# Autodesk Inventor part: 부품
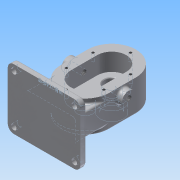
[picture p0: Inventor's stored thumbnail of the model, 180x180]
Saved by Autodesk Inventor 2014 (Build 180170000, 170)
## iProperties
Created: 2020-09
Part Number: 부품
Material: 알루미늄 6061
Document SubType Name: Modeling
Designer: net
Density: 2.71 g/cm^3
Appearance: 알루미늄 - 평지
Mass: 1445.06 g
Surface Area: 785.878 cm^2
Volume: 533.233 cm^3
Author: net
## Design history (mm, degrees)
sketch "스케치1"
  geometry: L1 (0, 0)-(0, 44); L2 (40, 0)-(40, 44); L3 (-40, 44)-(-40, 0); A1 r 40 centre (0, 0) between (-40, 0) and (40, 0); A2 r 40 centre (0, 44) between (40, 44) and (-40, 44); 1 further point
  constraints: 8 end point, 4 point on circle, 4 tangent, 2 centre point, 1 midpoint, 1 parallel, 1 vertical
  dimensions: "d0" = 44 distance of L1.start L1.end; "d1" = 80 diameter of A2
extrude "돌출1" new body sketch "스케치1" distance "d2" = 53; taper "d3" = 0 deg
sketch "스케치2"
  geometry: L1 (40, 0)-(40, 44) reference; L2 (0, 0)-(0, 44); L3 (24, 0)-(24, 44); L4 (-24, 44)-(-24, 0); A1 r 40 centre (0, 44) between (40, 44) and (-40, 44) reference; A2 r 40 centre (0, 0) between (-40, 0) and (40, 0) reference; A3 r 24 centre (0, 0) between (-24, 0) and (24, 0); A4 r 24 centre (0, 44) between (24, 44) and (-24, 44); 1 further point
  constraints: 8 end point, 4 point on circle, 4 tangent, 2 centre point, 2 parallel, 1 midpoint
  dimensions: "d4" = 48 diameter of A4
extrude "돌출2" cut sketch "스케치2" distance "d5" = 29; taper "d6" = 0 deg
sketch "스케치3"
  geometry: C1 r 19 at (0, 44); A1 r 40 centre (0, 44) between (40, 44) and (-40, 44) reference
  constraints: 1 centre point, 1 coincident
  dimensions: "d7" = 38 diameter of C1
extrude "돌출3" join sketch "스케치3" distance "d8" = 17; taper "d9" = 0 deg
sketch "스케치4"
  geometry: C1 r 8.5 at (0, 44); C2 r 12.5 at (0, 44); A1 r 24 centre (0, 44) between (24, 44) and (-24, 44) reference
  constraints: 2 centre point, 2 coincident
  dimensions: "d10" = 17 diameter of C1; "d11" = 25 diameter of C2
extrude "돌출4" cut sketch "스케치4" stored distance "d12" = 17; taper "d13" = 0 deg
extrude "돌출5" cut sketch "스케치4" distance "d14" = 15; taper "d15" = 0 deg
sketch "스케치6"
  geometry: L1 (-40, 0)-(-40, 53) reference; L2 (-40, 53)-(-24, 53) reference; L3 (-24, 53)-(-24, 24) reference; L4 (-24, 24)-(31.5, 24) reference; L5 (31.5, 24)-(31.5, 9) reference; L6 (31.5, 9)-(35.5, 9) reference; L7 (35.5, 9)-(35.5, -17) reference; L8 (35.5, -17)-(25, -17) reference; L9 (25, -17)-(25, 0) reference; L10 (25, 0)-(-40, 0) reference; L11 (84, 53)-(84, 0) reference; L12 (84, 0)-(63, 0) reference; L13 (63, 0)-(63, -17) reference; L14 (63, -17)-(52.5, -17) reference; L15 (52.5, -17)-(52.5, 9) reference; L16 (52.5, 9)-(56.5, 9) reference; L17 (56.5, 9)-(56.5, 24) reference; L18 (56.5, 24)-(68, 24) reference; L19 (68, 24)-(68, 53) reference; L20 (68, 53)-(84, 53) reference; L21 (52.5, -17)-(35.5, -17) reference; L22 (52.5, 9)-(35.5, 9) reference; L23 (44, -17)-(44, 9); L24 (52.5, -9)-(58, -9); L25 (58, -9)-(58, -16.3); L26 (58, -16.3)-(58.404, -17); 1 further point
  constraints: 8 end point, 2 midpoint, 2 perpendicular, 2 point on line
  dimensions: "d21" = 28 diameter of L25 L23; "d22" = 7.3 distance from line of L25.end L24; "d23" = 0.7 distance from line of L14 L25.end; "d24" = 30 deg angle of L25 L26
revolve "회전1" sketch "스케치6" stored, may be unused: angle "d25" = 90 deg
sketch "스케치8"
  geometry: C1 r 12.5 at (0, 0); A1 r 24 centre (0, 0) between (-24, 0) and (24, 0) reference
  constraints: 1 centre point, 1 coincident
  dimensions: "d27" = 25 diameter of C1
extrude "돌출6" cut sketch "스케치8" distance "d28" = 15; taper "d29" = 0 deg
fillet "모깎기1" dims "d30" = 0.5
chamfer "모따기1" distance "d31" = 1; stored, may be unused: second distance "d32" = 2, angle "d33" = 45 deg
sketch "스케치9"
  geometry: A1 r 24 centre (0, 44) between (24, 44) and (-24, 44) reference; A2 r 24 centre (0, 0) between (-24, 0) and (24, 0) reference; 6 further points
  constraints: 4 horizontal alignment, 2 vertical alignment
  dimensions: "d34" = 31 distance of A2.centre point (0, -31); "d35" = 31 distance of A1.centre point (0, 75); "d36" = 31 distance of A1.centre point (-31, 44); "d37" = 31 distance of point (31, 44) A1.centre; "d38" = 31 distance of A2.centre point (31, 0); "d39" = 31 distance of point (-31, 0) A2.centre
hole "구멍1" sketch "스케치9" at (0, 75), (0, -31), (31, 44), (-31, 44), (-31, 0), (31, 0) diameter "d40" = 4.134; stored, may be unused: countersink angle "d44" = 90 deg, drill point angle "d46" = 118 deg; dims "d41" = 10, "d42" = 4, "d43" = 2, "d45" = 12
node "작업 평면1"
sketch "스케치10"
  geometry: L1 (40, 53)-(-40, 53) reference; L2 (-19, -17)-(19, -17) reference; L3 (40, 0)-(40, 53) reference; L4 (-40, 0)-(-40, 53) reference; L5 (-60, -17)-(60, -17); L6 (60, -17)-(60, 83); L7 (60, 83)-(-60, 83); L8 (-60, 83)-(-60, -17); C1 r 4.5 at (50, 73); C2 r 4.5 at (50, -7); C3 r 4.5 at (-50, -7); C4 r 4.5 at (-50, 73); 1 further point
  constraints: 8 end point, 4 centre point, 2 parallel, 2 vertical alignment, 1 collinear, 1 horizontal, 1 horizontal alignment, 1 perpendicular
  dimensions: "d48" = 100 distance between parallel lines of L5 L7; "d49" = 120 distance between parallel lines of L8 L6; "d50" = 60 distance from line of point (0, 0) L6; "d51" = 9 diameter of C1; "d52" = 9 diameter of C2; "d53" = 9 diameter of C3; "d54" = 9 diameter of C4; "d55" = 10 distance from line of L6 C1.centre; "d56" = 10 distance from line of L7 C1.centre; "d57" = 10 distance from line of L8 C4.centre; "d58" = 10 distance from line of L7 C4.centre; "d59" = 10 distance from line of L5 C2.centre
extrude "돌출7" join sketch "스케치10" distance "d60" = 10; taper "d61" = 0 deg
fillet "모깎기2" dims "d62" = 10
sketch "스케치13"
  geometry: L1 (-60, 7)-(-60, -73) reference; L2 (50, 17)-(-50, 17) reference; L3 (-40, -8)-(40, -8); L4 (40, -8)-(40, -45); L5 (40, -45)-(-40, -45); L6 (-40, -45)-(-40, -8); 1 further point
  constraints: 8 end point, 2 parallel, 1 horizontal, 1 perpendicular
  dimensions: "d65" = 80 distance between parallel lines of L4 L6; "d66" = 25 distance between parallel lines of L3 L2; "d67" = 37 distance between parallel lines of L5 L3; "d68" = 20 distance between parallel lines of L1 L6
extrude "돌출8" join sketch "스케치13" stored distance "d69" = 10; taper "d70" = 0 deg
sketch "스케치14"
  geometry: L1 (-60, 7)-(-60, -73) reference; L2 (-50, -83)-(50, -83) reference; 2 further points
  constraints: 1 other
  dimensions: "d71" = 12 distance from line of L2 point (0, -71); "d72" = 60 distance from line of L1 point (0, -71)
feature "엠보싱1" sketch "스케치14" dims "d0" = 44, "d1" = 80, "d73" = 0.5, "d74" = 0
node "작업 평면2"
sketch "스케치15"
  geometry: L1 (-19, -17)-(19, -17) reference; L2 (40, 0)-(40, 53) reference; L3 (-44, 53)-(0, 53) reference; C1 r 11 at (-22, 39); 2 further points
  constraints: 1 centre point
  dimensions: "d75" = 22 diameter of C1; "d76" = 22 horizontal distance of C1.centre point (0, 0); "d77" = 14 distance from line of L3 C1.centre
extrude "돌출9" join sketch "스케치15" distance "d78" = 10; taper "d79" = 0 deg
sketch "스케치16"
  geometry: C1 r 11 at (0, 0) reference; 2 further points
  constraints: 1 coincident
hole "구멍2" sketch "스케치16" at (0, 0) diameter "d80" = 8.376; stored, may be unused: countersink angle "d84" = 90 deg, drill point angle "d86" = 118 deg; dims "d81" = 10, "d82" = 4, "d83" = 2, "d85" = 12
fillet "모깎기3" dims "d87" = 3
fillet "모깎기4" dims "d88" = 3
fillet "모깎기5" dims "d89" = 3
fillet "모깎기6" dims "d90" = 3
fillet "모깎기7" dims "d91" = 3
node "솔리드1"
mirror "대칭1"
node "절단 모서리 투영1"
other parameters: "d47" = -68
